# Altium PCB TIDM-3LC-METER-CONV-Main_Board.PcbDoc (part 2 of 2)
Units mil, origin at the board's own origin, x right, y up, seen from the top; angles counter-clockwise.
Board outline 4050 x 4800 mil, 4 copper layers (Top Layer, Mid-Layer 1, Mid-Layer 2, Bottom Layer); 180 components, 206 nets, 819 pads, 257 vias.
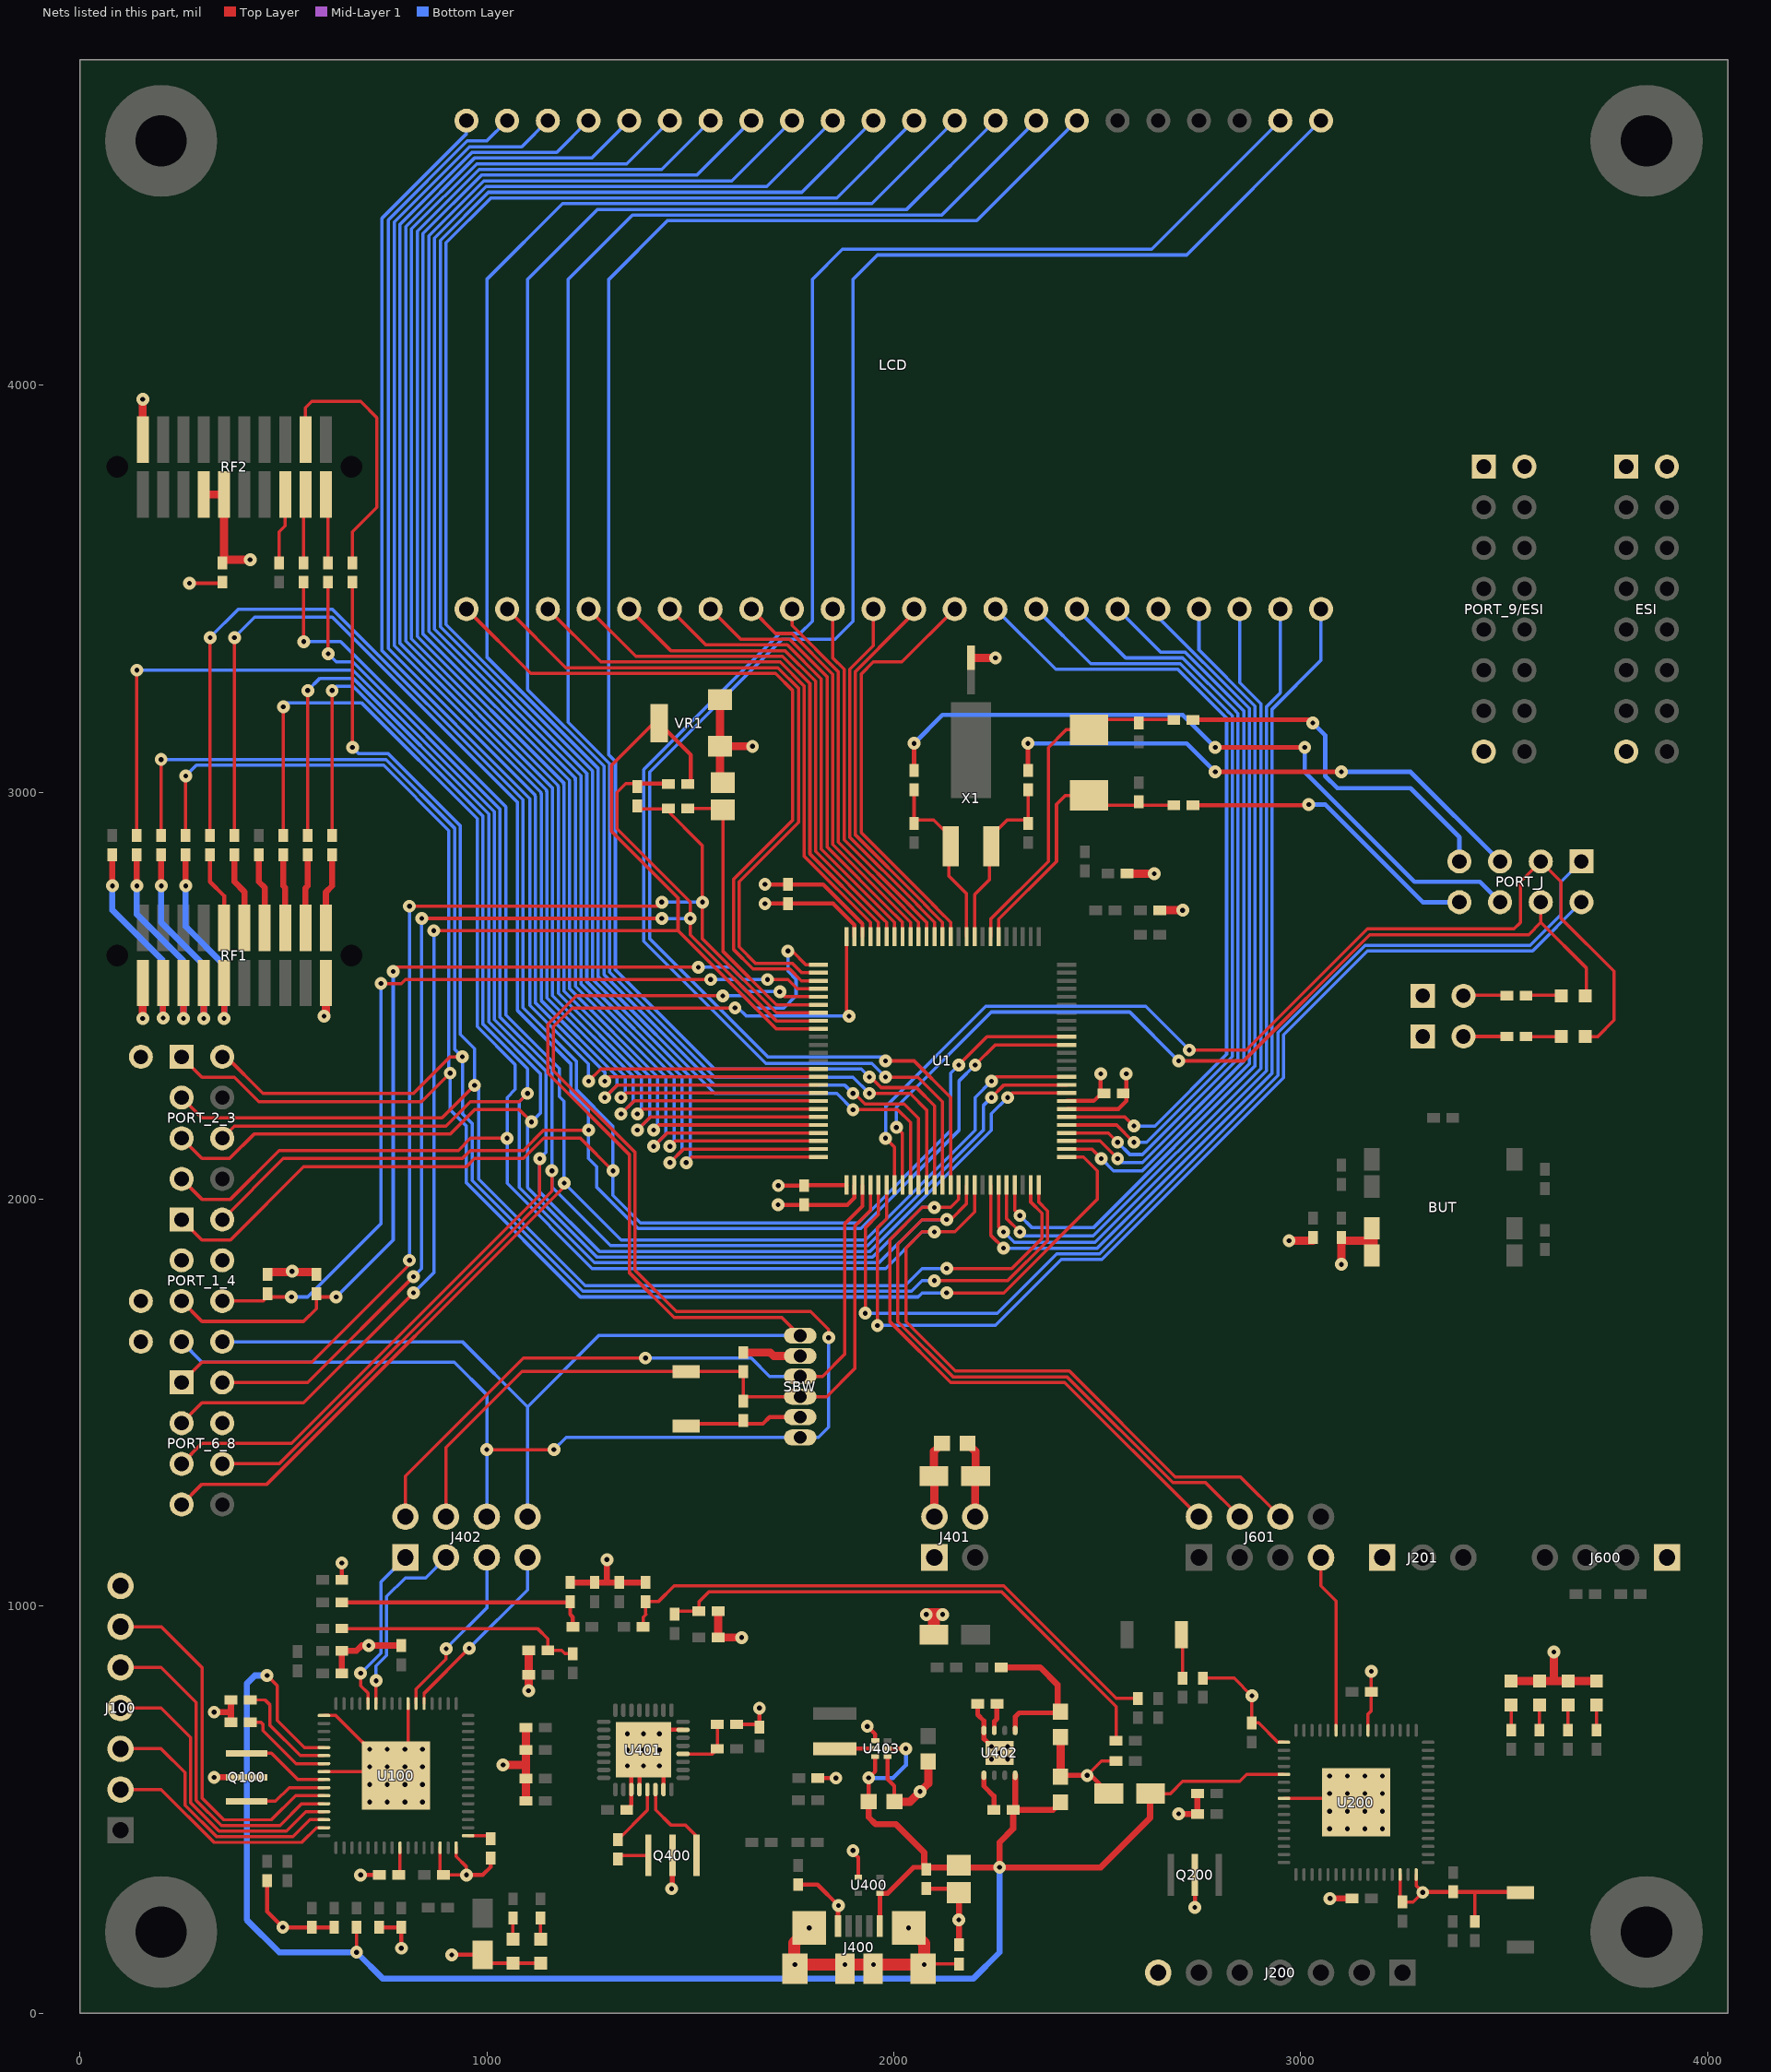
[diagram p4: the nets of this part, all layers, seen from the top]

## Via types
v1: diameter 31.5, hole 11.81, Top Layer to Bottom Layer, tented both sides, 211 vias
v2: diameter 31.5, hole 11.81, Top Layer to Bottom Layer, tented bottom, 41 vias
v3: diameter 23.81, hole 11.81, Top Layer to Bottom Layer, tented bottom, 5 vias

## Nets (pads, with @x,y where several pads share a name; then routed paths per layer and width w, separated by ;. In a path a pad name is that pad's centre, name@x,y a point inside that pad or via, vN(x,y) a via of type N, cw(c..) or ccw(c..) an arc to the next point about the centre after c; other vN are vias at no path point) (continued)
EZFET_SBW_RST: J402.3 U100.43 | length 473.6
  Top Layer w7.87: U100.43@727.79,761.17 v1(727.79,817.21) ; J402.3@900,1130 J402.3@910,1140
  Bottom Layer w7.87: v1(727.79,817.21) 727.79,853.17 753.87,879.25 753.87,1023.87 800,1070 850,1070 J402.3@900,1120
EZFET_SBW_TST: J402.1 U100.44 | length 412.5
  Top Layer w7.87: v1(690,836) 690,805 708.1,786.9 U100.44@708.1,761.17
  Bottom Layer w7.87: v1(690,836) 691,836 740,885 740,1060 J402.1@800,1120
EZFET_TCK: J100.2 U100.63 | length 568.6
  Top Layer w7.87: J100.2@100,550 200,550 330,420 545,420 581.05,456.05 U100.63@599.83,456.05
EZFET_TDI: J100.4 U100.61 | length 738.7
  Top Layer w7.87: J100.4@100,750 200,750 272.25,677.75 272.25,517.37 341.87,447.75 507.75,447.75 555.42,495.42 U100.61@599.83,495.42
EZFET_TDO: J100.5 U100.60 | length 823.9
  Top Layer w7.87: J100.5@100,850 200,850 286.13,763.87 286.13,523.12 347.62,461.62 491.62,461.62 545.1,515.1 U100.60@599.83,515.1
EZFET_TEST: J100.6 U100.59 | length 908.8
  Top Layer w7.87: J100.6@100,950 200,950 300,850 300,529.54 354.04,475.5 470.5,475.5 530,535 565,535 565.21,534.79 U100.59@599.83,534.79
EZFET_TMS: J100.3 U100.62 | length 653.6
  Top Layer w7.87: J100.3@100,650 200,650 258.38,591.62 258.38,511.62 336.13,433.87 523.87,433.87 565.73,475.73 U100.62@599.83,475.73
EZFET_UART_RXD: J402.5 U100.38 | length 430.8
  Top Layer w7.87: U100.38@826.21,761.17 826.21,796.21 900,870 v1(900,896)
  Bottom Layer w7.87: v1(900,896) 1000,996 J402.5@1000,1120
EZFET_UART_TXD: J402.7 U100.37 | length 464.1
  Top Layer w7.87: U100.37@845.9,761.17 845.9,785.9 v1(957,897)
  Bottom Layer w7.87: v1(957,897) 1100,1040 J402.7@1100,1120
EZFET_V18: C106.1 U100.55 | length 232
  Top Layer w7.87: C106.1@418.62,715 445,715 450,710 450,695 531.47,613.53 U100.55@599.83,613.53
EZFET_VCORE: C107.1 U100.17 | length 59
  Top Layer w7.87: U100.17@954.16,436.36 1002.26,436.36 C107.1@1010,428.62
EZFET_VREF: C108.1 U100.9 | length 72.6
  Top Layer w7.87: U100.9@786.84,406.83 786.84,336.78 C108.1@788.62,335
EZFET_VUSB: C105.1 U100.54 | length 267.2
  Top Layer w7.87: C105.1@418.62,770 455,770 467.5,757.5 467.5,707.5 541.79,633.21 U100.54@599.83,633.21
EZFET_XT2IN: Q100.1 U100.57 | length 216.7
  Top Layer w7.87: Q100.1@410,639.06 470.94,639.06 535.84,574.16 U100.57@599.83,574.16
EZFET_XT2OUT: Q100.3 U100.58 | length 203.7
  Top Layer w7.87: Q100.3@410,520.94 480.94,520.94 514.47,554.47 U100.58@599.83,554.47
GND: C100.2 C101.2 C102.2 C103.2 C104.2 C105.2 C106.2 C107.2 C108.2 C109.2 C110.2 C111.2 C200.2 C201.2 C202.2 C203.2 C204.2 C205.2 C206.2 C207.2 C208.2 C209.2 C210.2 C400.2 C401.2 C402.2 C403.2 C404.2 C405.2 C406.2 C407.2 C408.2 C410.2 C412.2 C414.2 C415.2 C416.2 C417.2 C418.2 D100.2 D101.2 D200.2 D201.2 D202.2 D203.2 J100.7 J200.7 J201.1 J400.5 J401.1 J600.1 Q100.2 Q200.2 Q400.2 R102.2 R107.1 R109.1 R210.1 R400.1 R401.1 R402.1 R403.1 R405.2 R410.1 R411.1 R414.1 R415.1 S201.1 U100.14 U100.16 U100.39 U100.49 U100.56 U100.65 U200.14 U200.16 U200.39 U200.49 U200.56 U200.65 U400.4 U401.7 U401.27 U401.28 U401.31 U401.33 U402.4 U402.9 U403.1 U403.4 | length 6226.4
  Top Layer w7.87: R210.1@2760,823.62 2836.38,823.62 v1(2880,780) C200.2@2880,713.62 2896.38,713.62 2944.12,665.88 U200.49@2958.92,665.88 ; U200.56@2958.92,528.08 3061.92,528.08 3071.76,518.24 U200.65@3136.08,518.24 v2(3157.73,539.9) U200.65@3165.61,547.77 ; U200.39@3165.61,695.41 3165.61,735.61 3173.62,743.62 C202.2@3173.62,790 v1(3173.62,840) ; U200.14@3244.35,341.08 3244.35,273.62 3276.46,273.62 v1(3300,297.16) 3283.72,313.44 U200.16@3283.72,341.08 ; C210.2@3428.19,225.78 3428.19,296.73
  Top Layer w8: U100.56@599.83,593.84 767.16,593.84 U100.65@777,584 ; U100.49@599.83,731.64 629.36,731.64 v2(755.35,605.65) ; U100.65@806.53,613.53 U100.39@806.53,761.17 ; U100.14@885.27,406.83 885.27,348.35 C102.2@893.62,340 v1(950,340) 950,360 924.64,385.36 U100.16@924.64,406.83 ; v1(2475.35,584.65) 2510.71,620 C201.2@2546.38,620
  Top Layer w10: C111.2@460,326.38 460,250 v1(498.62,211.38) R109.1@570,211.38 C110.2@625,211.38 ; C101.2@643.62,1065 v1(643.62,1106.38) ; v1(690,340) C108.2@736.38,340 ; C109.2@735,211.38 R107.1@790,211.38 v1(790,160) ; U100.65@777,584 v2(798.65,605.65) U100.65@806.53,613.53 ; v1(913.82,143.82) C103.2@990,143.82 1010.65,123.17 D100.2@1064.44,123.17 D101.2@1132.16,123.17 ; v1(950,340) 990,340 1010,360 C107.2@1010,381.38 C107.2@1010,391.38 ; C408.2@1343.62,500 1355.32,511.69 U401.27@1355.32,549.84 1355.32,598.07 v2(1345.47,607.91) ; U401.28@1375,549.84 1375,598.07 v2(1384.84,607.91) ; v2(1424.21,607.91) 1434.06,598.07 U401.31@1434.06,549.84 ; v2(1424.21,686.65) 1434.06,696.5 U401.7@1482.28,696.5 ; C400.2@1613.62,710 1663.62,710 C407.2@1670,703.62 v1(1670,750) ; C403.2@1765,316.38 1812.76,316.38 v1(1864.45,264.68) ; C404.2@1813.62,578 v1(1858,578) ; v1(1900,400) 1900,395.75 1912.87,382.87 U400.4@1912.87,334.37 ; v1(1935,705) 1954.68,685.32 U403.1@1954.68,670 ; U403.4@1985,630.63 1985,575.16 2001.34,558.82 C415.2@2001.34,520 ; C402.2@2080,306.38 2140.16,306.38 C401.2@2160,286.54 ; v1@2484.17,584.65 C209.2@2528.82,540 ; v1(2740,260) Q200.2@2740,340 ; U200.65@3136.08,518.24 v2(3201.04,453.28) U200.65@3201.92,454.16 ; v1(3300,297.16) 3301.38,298.54 C208.2@3375,298.54 3538.39,298.54 S201.1@3540,296.93
  Top Layer w12: v1(1454.15,306.15) 1456,308 Q400.2@1456,388 ; J400.5@1863.27,214.68 v1@1863.27,263.5 ; C416.2@2206.38,760 2206.38,733.62 2221.61,718.39 U402.4@2221.61,695.12 2221.61,674.45 v3(2240.32,655.75) ; C414.2@2410,584.65 v1(2475.35,584.65)
  Top Layer w15: v1(330,580) Q100.2@410,580 ; v1(330,740) 371.38,740 ; C106.2@371.38,715 371.38,740 ; C105.2@371.38,770 371.38,740 ; C100.2@643.62,835.5 R102.2@643.62,890.5 679.5,890.5 692.62,903.62 C104.2@790,903.62 ; R411.1@1205,1058.62 C406.2@1265,1058.62 1295.25,1058.62 ; v1(1295.25,1114.75) 1295.25,1058.62 ; R414.1@1390.5,1058.62 C410.2@1325.5,1058.62 1295.25,1058.62 ; R405.2@2160,168.62 C401.2@2160,286.54 ; v1(2700,490) C207.2@2746.38,490 C206.2@2746.38,540 ; v1(3072.16,282.16) C204.2@3126.38,282.16
  Top Layer w20: v1(1040,610) 1096.22,610 ; R402.1@1096.22,521.97 R403.1@1096.22,576.97 1096.22,610 ; R401.1@1096.22,701.97 R400.1@1096.22,646.97 1096.22,610 ; v1(1102.69,792.69) C405.2@1102.69,831.65 R410.1@1102.69,891.65 ; R415.1@1568.62,988.35 1568.62,961.38 C412.2@1568.62,923.35 v1(1626.65,923.35) ; C415.2@2001.34,520 2040,520 v1(2065,545) 2085,565 C417.2@2085,610 ; C418.2@2402.42,678.15 2410,670.57 C414.2@2410,584.65 ; D203.2@3517,816.69 D202.2@3587,816.69 3622,816.69 ; v1(3622,888) 3622,816.69 ; D200.2@3727,816.69 D201.2@3657,816.69 3622,816.69
  Top Layer w30: v1(2080,980) v1(2120,980) ; C203.2@2098.82,930 2098.82,978.82
  other v1: 2160,230 710,903.62
  other v2: 3071.12,453.28 3114.43,453.28 3157.73,453.28 3071.12,496.59 3114.43,496.59 3157.73,496.59 3201.04,496.59 712.04,519.04 755.35,519.04 798.65,519.04 841.96,519.04 3071.12,539.9 3114.43,539.9 3201.04,539.9 712.04,562.35 755.35,562.35 798.65,562.35 841.96,562.35 3071.12,583.2 3114.43,583.2 3157.73,583.2 3201.04,583.2 712.04,605.65 841.96,605.65 1345.47,647.28 1384.84,647.28 1424.21,647.28 712.04,648.96 755.35,648.96 798.65,648.96 841.96,648.96 1345.47,686.65 1384.84,686.65
  other v3: 2240.32,624.25 2279.68,624.26 2260,640 2279.68,655.75
HFXIN: PORT_J.7 R61.1 | length 884.4
  Top Layer w11.02: R61.1@2743.49,3178 3022,3178 v1(3030,3170)
  Bottom Layer w11.02: v1(3030,3170) 3060,3140 3060,3040 3090,3010 3270,3010 3390,2890 PORT_J.7@3390,2830
HFXOUT: PORT_J.8 R62.1 | length 747.9
  Top Layer w11.02: R62.1@2743.49,2968 3020,2968 v1(3020,2970)
  Bottom Layer w11.02: v1(3020,2970) 3060,2970 3300,2730 PORT_J.8@3390,2730
HUB_DM1: R203.1 R415.2 R417.1 | length 1322.1
  Top Layer w7.87: R417.1@1461.65,980.43 1469.57,988.35 R415.2@1521.38,988.35 1521.38,1011.38 1546.13,1036.13 2264.25,1036.13 2546.38,754 R203.1@2546.38,670
HUB_DM2: R101.1 R411.2 R413.1 | length 626
  Top Layer w10: R101.1@643.62,1010 1203.62,1010 R411.2@1205,1011.38 1205,980 1211.38,973.62 R413.1@1211.38,950
HUB_DP1: R201.1 R414.2 R416.1 | length 1404.4
  Top Layer w7.87: R416.1@1384.12,950 1384.12,973.12 1391,980 1390.5,980.5 R414.2@1390.5,1011.38 1421.38,1011.38 1460,1050 2270,1050 2546.38,773.62 R201.1@2600,773.62
HUB_DP2: R100.1 R410.2 R412.1 | length 610
  Top Layer w7.87: R410.2@1149.93,891.65 1184.16,891.65 1192.19,883.62 R412.1@1211.31,883.62
  Top Layer w8: R100.1@643.62,945.5 1124.5,945.5 1149.93,920.07 R410.2@1149.93,891.65
HUB_R\E\S\E\T\: C400.1 R404.1 U401.4 | length 149.3
  Top Layer w8: U401.4@1482.28,637.44 1553.82,637.44 R404.1@1566.38,650 C400.1@1566.38,710
HUB_XTAL1: Q400.1 U401.30 | length 232.2
  Top Layer w7.87: U401.30@1414.37,549.84 1415,549.21 1415,500 1452,463 1488,463 1514.06,436.94 Q400.1@1514.06,380
HUB_XTAL2: R406.2 U401.29 | length 153.3
  Top Layer w7.87: R406.2@1322,426.62 1394.69,499.31 U401.29@1394.69,549.84
I2C_SCL: PORT_1_4.6 R40.1 U1.5 | length 2189.5
  Top Layer w8: PORT_1_4.6@350,1750 451.49,1750 461.49,1760 v1(520,1760) ; v1(740,2530) 790,2530 800,2540 1560,2540 1550,2530 v1(1550,2540) ; v1(1720,2510) 1732.52,2497.48 U1.5@1814.88,2497.48
  Bottom Layer w8: v1(520,1760) 560,1760 740,1940 v1(740,2530) ; v1(1550,2540) 1609.8,2540 1639.8,2510 v1(1720,2510)
I2C_SDA: PORT_1_4.5 R41.1 U1.4 | length 2371.2
  Top Layer w8: PORT_1_4.5@250,1750 300,1700 550,1700 581.49,1731.49 581.49,1760 v1(630,1760) ; v1(770,2560) 780,2570 v1(1520,2570) ; v1(1690,2540) 1740,2540 1762.83,2517.17 U1.4@1814.88,2517.17
  Bottom Layer w8: v1(630,1760) 770,1900 v1(770,2560) ; v1(1520,2570) 1599.6,2570 1629.6,2540 v1(1690,2540)
LCD0: LCD.1 U1.3 | length 1821.7
  Top Layer w8: LCD.1@950,3450 1108,3292 1709.41,3292 1752,3249.41 1752,2931.8 1606,2785.8 1606,2614.2 1654.2,2566 1744,2566 1773.15,2536.85 U1.3@1814.88,2536.85
LCD1: LCD.2 U1.2 | length 1713.5
  Top Layer w8: LCD.2@1050,3450 1194,3306 1715.21,3306 1766,3255.21 1766,2926 1620,2780 1620,2620 1660,2580 1750,2580 1773.46,2556.54 U1.2@1814.88,2556.54
LCD2: LCD.3 U1.97 | length 1391.6
  Top Layer w8: LCD.3@1150,3450 1280,3320 1721.01,3320 1780,3261.01 1780,2842.83 1942.83,2680 U1.97@1942.83,2645.12
LCD3: LCD.4 U1.96 | length 1311.4
  Top Layer w8: LCD.4@1250,3450 1366,3334 1726.8,3334 1794,3266.8 1794,2848.63 1956.83,2685.8 1956.83,2685.69 1962.52,2680 U1.96@1962.52,2645.12
LCD4: LCD.5 U1.95 | length 1231.1
  Top Layer w8: LCD.5@1350,3450 1452,3348 1732.6,3348 1808,3272.6 1808,2854.43 1970.83,2691.6 1970.83,2691.48 1976.52,2685.8 1976.52,2685.68 1982.2,2680 U1.95@1982.2,2645.12
LCD5: LCD.6 U1.94 | length 1150.9
  Top Layer w8: LCD.6@1450,3450 1538,3362 1738.4,3362 1822,3278.4 1822,2860.23 1984.83,2697.4 1984.83,2697.28 1990.52,2691.6 1990.52,2691.48 1996.2,2685.8 1996.2,2685.69 2001.89,2680 U1.94@2001.89,2645.12
LCD6: LCD.7 U1.93 | length 1070.6
  Top Layer w8: LCD.7@1550,3450 1624,3376 1744.2,3376 1836,3284.2 1836,2866.03 1998.83,2703.2 1998.83,2703.08 2004.52,2697.4 2004.52,2697.28 2010.2,2691.6 2010.2,2691.48 2015.89,2685.8 2015.89,2685.69 2021.58,2680 U1.93@2021.58,2645.12
LCD7: LCD.8 U1.92 | length 990.4
  Top Layer w8: LCD.8@1650,3450 1710,3390 1750,3390 1850,3290 1850,2871.83 2012.83,2708.99 2012.83,2708.88 2018.52,2703.2 2018.52,2703.08 2024.2,2697.4 2024.2,2697.28 2029.89,2691.6 2029.89,2691.48 2035.58,2685.8 2035.58,2685.68 2041.26,2680 U1.92@2041.26,2645.12
LCD8: LCD.9 U1.91 | length 933.7
  Top Layer w8: LCD.9@1750,3450 1750,3410 1864,3296 1864,2877.63 2026.83,2714.79 2026.83,2714.68 2032.52,2708.99 2032.52,2708.88 2038.2,2703.2 2038.2,2703.08 2043.89,2697.4 2043.89,2697.28 2049.58,2691.6 2049.58,2691.48 2055.26,2685.8 2055.26,2685.69 2060.95,2680 U1.91@2060.95,2645.12
LCD9: LCD.10 U1.90 | length 900.4
  Top Layer w8: LCD.10@1850,3450 1850,3330 1878,3302 1878,2883.43 2040.83,2720.59 2040.83,2720.48 2046.52,2714.79 2046.52,2714.68 2052.2,2708.99 2052.2,2708.88 2057.89,2703.2 2057.89,2703.08 2063.58,2697.4 2063.58,2697.28 2069.26,2691.6 2069.26,2691.48 2074.95,2685.8 2074.95,2685.68 2080.63,2680 U1.90@2080.63,2645.12
LCD10: LCD.11 U1.89 | length 915.2
  Top Layer w8: LCD.11@1950,3450 1950,3360 1892,3302 1892,2889.23 2054.83,2726.39 2054.83,2726.28 2060.52,2720.59 2060.52,2720.48 2066.2,2714.79 2066.2,2714.68 2071.89,2708.99 2071.89,2708.88 2077.58,2703.2 2077.58,2703.08 2083.26,2697.4 2083.26,2697.28 2088.95,2691.6 2088.95,2691.48 2094.63,2685.8 2094.63,2685.69 2100.32,2680 U1.89@2100.32,2645.12
LCD11: LCD.12 U1.88 | length 953.2
  Top Layer w8: LCD.12@2050,3450 2050,3441 1964,3355 1964,3354.2 1906,3296.2 1906,2895.02 2068.83,2732.19 2068.83,2732.08 2074.52,2726.39 2074.52,2726.28 2080.2,2720.59 2080.2,2720.48 2085.89,2714.79 2085.89,2714.68 2091.58,2708.99 2091.58,2708.88 2097.26,2703.2 2097.26,2703.08 2102.95,2697.4 2102.95,2697.28 2108.63,2691.6 2108.63,2691.48 2114.32,2685.8 2114.32,2685.68 2120,2680 U1.88@2120,2645.12
LCD12: LCD.13 U1.87 | length 1032.4
  Top Layer w8: U1.87@2139.69,2645.12 2139.69,2680 2134,2685.69 2134,2685.8 2128.32,2691.48 2128.32,2691.6 2122.63,2697.28 2122.63,2697.4 2116.95,2703.08 2116.95,2703.2 2111.26,2708.88 2111.26,2708.99 2105.58,2714.68 2105.58,2714.79 2099.89,2720.48 2099.89,2720.59 2094.2,2726.28 2094.2,2726.39 2088.52,2732.08 2088.52,2732.19 2082.83,2737.88 2082.83,2737.99 1920,2900.82 1920,3290.4 1949.6,3320 2020,3320 LCD.13@2150,3450
LCD13: LCD.14 U1.56 | length 1979.8
  Top Layer w8: U1.56@2425.12,2202.2 2567.8,2202.2 v1(2590,2180)
  Bottom Layer w8: LCD.14@2250,3450 2398,3302 2698,3302 2818,3182 2818,2356.39 2641.61,2180 v1(2590,2180)
LCD14: LCD.15 U1.55 | length 1939.7
  Top Layer w8: U1.55@2425.12,2182.52 2547.48,2182.52 v1(2590,2140)
  Bottom Layer w8: LCD.15@2350,3450 2484,3316 2704,3316 2820,3200 2820,3199.8 2832,3187.8 2832,2350.59 2621.41,2140 v1(2590,2140)
LCD15: LCD.16 U1.54 | length 1891.3
  Top Layer w8: U1.54@2425.12,2162.83 2527.17,2162.83 v1(2550,2140)
  Bottom Layer w8: LCD.16@2450,3450 2570,3330 2710,3330 2840,3200 2840,3199.6 2846,3193.6 2846,2344.79 2611.21,2110 2580,2110 v1(2550,2140)
LCD16: LCD.17 U1.53 | length 1834.6
  Top Layer w8: U1.53@2425.12,2143.15 2506.85,2143.15 v1(2550,2100)
  Bottom Layer w8: v1(2550,2100) 2560,2090 2611.01,2090 2860,2338.99 2860,3200 2716,3344 2656,3344 LCD.17@2550,3450
LCD17: LCD.18 U1.52 | length 1789.6
  Top Layer w8: U1.52@2425.12,2123.46 2486.54,2123.46 v1(2510,2100)
  Bottom Layer w8: v1(2510,2100) 2540,2070 2610.8,2070 2874,2333.2 2874,3205.8 2650,3429.8 LCD.18@2650,3450
LCD18: LCD.19 U1.47@2297.17,2034.88 | length 2015
  Top Layer w8: U1.47@2297.17,2034.88 2297.17,1972.83 v1(2310,1960)
  Bottom Layer w8: v1(2310,1960) 2340,1930 2490.6,1930 2888,2327.4 2888,3211.6 2750,3349.6 LCD.19@2750,3450
LCD19: LCD.20 U1.46 | length 2045.3
  Top Layer w8: U1.46@2277.48,2034.88 2277.48,1952.52 v1(2310,1920)
  Bottom Layer w8: v1(2310,1920) 2320,1910 2490.4,1910 2902,2321.6 2902,3215.8 2902.5,3216.3 2902,3216.79 2902,3217.4 2850,3269.4 LCD.20@2850,3450
LCD20: LCD.21 U1.45 | length 2099.7
  Top Layer w8: U1.45@2257.8,2034.88 2257.8,1932.2 v1(2270,1920)
  Bottom Layer w8: v1(2270,1920) 2296,1894 2494.2,1894 2916,2315.8 2916,3210 2950,3244 LCD.21@2950,3450
LCD21: LCD.22 U1.44 | length 2195.9
  Top Layer w8: U1.44@2238.11,2034.88 2238.11,1911.89 v1(2270,1880)
  Bottom Layer w8: v1(2270,1880) 2500,1880 2930,2310 2930,3204.2 3050,3324.2 LCD.22@3050,3450
LCD22: LCD.23 U1.39 | length 4331.3
  Top Layer w8: v1(1980,2340) 2050,2340 2139.68,2250.32 U1.39@2139.68,2034.88
  Bottom Layer w8: v1(1980,2340) 1970,2350 1690,2350 1400,2640 1400,3050 1726,3376 1856,3376 1900,3420 1900,4260 1960,4320 2720,4320 LCD.23@3050,4650
LCD23: LCD.24 U1.38 | length 4240.5
  Top Layer w8: v1(1980,2300) 2060,2300 2120,2240 U1.38@2120,2034.88
  Bottom Layer w8: v1(1980,2300) 1946,2334 1686,2334 1386,2634 1386,3055.8 1720.2,3390 1770,3390 1800,3420 1800,4260 1874,4334 2634,4334 LCD.24@2950,4650
LCD24: LCD.29 U1.37 | length 4132.1
  Top Layer w8: v1(1940,2300) 1943.59,2300 1969.33,2274.25 2055.75,2274.25 2100.31,2229.69 U1.37@2100.31,2034.88
  Bottom Layer w8: v1(1940,2300) 1920,2320 1559.51,2320 1316,2563.51 1316,3075.56 1300,3091.56 1300,4260 1444,4404 2204,4404 LCD.29@2450,4650
LCD25: LCD.30 U1.36 | length 4159.3
  Top Layer w8: v1(1940,2260) 2040,2260 2080.63,2219.37 U1.36@2080.63,2034.88
  Bottom Layer w8: v1(1940,2260) 1900,2300 1559.71,2300 1302,2557.71 1302,3069.76 1200,3171.76 1200,4260 1358,4418 2118,4418 LCD.30@2350,4650
LCD26: LCD.31 U1.35 | length 4180.8
  Top Layer w8: v1(1900,2260) 1903.59,2260 1929.33,2234.25 2025.75,2234.25 2060.94,2199.06 U1.35@2060.94,2034.88
  Bottom Layer w8: v1(1900,2260) 1880,2280 1559.91,2280 1288,2551.91 1288,3063.97 1100,3251.97 1100,4260 1272,4432 2032,4432 LCD.31@2250,4650
LCD27: LCD.32 U1.34 | length 4208.1
  Top Layer w8: v1(1900,2220) 2010,2220 2041.26,2188.74 U1.34@2041.26,2034.88
  Bottom Layer w8: v1(1900,2220) 1860,2260 1560.11,2260 1274,2546.11 1274,3058.17 1000,3332.17 1000,4260 1186,4446 1946,4446 LCD.32@2150,4650
LCD28: LCD.33 U1.25 | length 4127.5
  Top Layer w8: v1@1480,2090 v1(1490,2090) 1503.78,2103.78 U1.25@1814.88,2103.78
  Bottom Layer w8: v1(1490,2090) 1500,2100 1500,2300.31 1260,2540.31 1260,3052.37 900,3412.37 900,4350 1010,4460 1860,4460 LCD.33@2050,4650
LCD29: LCD.34 U1.24 | length 4089.1
  Top Layer w8: v1(1450,2090) 1483.46,2123.46 U1.24@1814.88,2123.46
  Bottom Layer w8: v1(1450,2090) 1480,2120 1480,2300.52 1245.72,2534.8 1245.72,3046.45 885.72,3406.45 885.72,4355.51 1004.2,4474 1774,4474 LCD.34@1950,4650
LCD30: LCD.35 U1.23 | length 3957.4
  Top Layer w8: v1@1440,2130 v1(1450,2130) 1463.15,2143.15 U1.23@1814.88,2143.15
  Bottom Layer w8: v1(1450,2130) 1460,2140 1460,2300.72 1231.72,2529 1231.72,3036.47 1231.57,3036.62 1231.57,3040.59 871.57,3400.59 871.57,4361.17 998.4,4488 1688,4488 LCD.35@1850,4650
LCD31: LCD.36 U1.22 | length 3918.9
  Top Layer w8: v1(1410,2130) 1442.83,2162.83 U1.22@1814.88,2162.83
  Bottom Layer w8: v1(1410,2130) 1440,2160 1440,2300.92 1217.72,2523.2 1217.72,3030.68 1217.43,3030.96 1217.43,3034.73 857.43,3394.73 857.43,4366.83 992.6,4502 1602,4502 LCD.36@1750,4650
LCD32: LCD.37 U1.21 | length 3777.2
  Top Layer w8: v1(1410,2170) 1422.52,2182.52 U1.21@1814.88,2182.52
  Bottom Layer w8: v1(1410,2170) 1420,2180 1420,2301.12 1203.72,2517.4 1203.72,3024.88 1203.29,3025.3 1203.29,3028.88 843.29,3388.88 843.29,4372.48 986.8,4516 1516,4516 LCD.37@1650,4650
LCD33: LCD.38 U1.20 | length 3748.7
  Top Layer w8: v1(1370,2170) 1402.2,2202.2 U1.20@1814.88,2202.2
  Bottom Layer w8: v1(1370,2170) 1400,2200 1400,2301.32 1189.72,2511.6 1189.72,3019.08 1189.15,3019.65 1189.15,3023.02 829.15,3383.02 829.15,4378.14 981.01,4530 1430,4530 LCD.38@1550,4650
LCD34: LCD.39 U1.19 | length 3607
  Top Layer w8: v1(1370,2210) 1381.89,2221.89 U1.19@1814.88,2221.89
  Bottom Layer w8: v1(1370,2210) 1380,2220 1380,2301.52 1175.72,2505.8 1175.72,3013.28 1175.01,3013.99 1175.01,3017.16 815.01,3377.16 815.01,4383.8 975.21,4544 1344,4544 LCD.39@1450,4650
LCD35: LCD.40 U1.18 | length 3578.5
  Top Layer w8: v1(1330,2210) 1361.57,2241.57 U1.18@1814.88,2241.57
  Bottom Layer w8: v1(1330,2210) 1360,2240 1360,2301.72 1161.72,2500.01 1161.72,3007.48 1160.86,3008.33 1160.86,3011.3 800.86,3371.3 800.86,4389.46 969.41,4558 1258,4558 LCD.40@1350,4650
LCD36: LCD.41 U1.17 | length 3446.7
  Top Layer w8: v1@1320,2250 v1(1330,2250) 1341.26,2261.26 U1.17@1814.88,2261.26
  Bottom Layer w8: LCD.41@1250,4650 1172,4572 963.61,4572 786.86,4395.25 786.86,3365.5 1138.66,3013.71 1146.86,3005.5 1146.86,3002.53 1147.72,3001.68 1147.72,2494.21 1340,2301.92 1340,2260 v1(1330,2250)
LCD37: LCD.42 U1.16 | length 3408.1
  Top Layer w8: v1(1290,2250) 1320.94,2280.94 U1.16@1814.88,2280.94
  Bottom Layer w8: LCD.42@1150,4650 1086,4586 957.81,4586 772.86,4401.05 772.86,3359.71 1132.86,2999.71 1132.86,2996.73 1133.72,2995.88 1133.72,2488.41 1320,2302.12 1320,2280 v1(1290,2250)
LCD38: LCD.43 U1.15 | length 3258.7
  Top Layer w8: v1(1290,2290) 1300.63,2300.63 U1.15@1814.88,2300.63
  Bottom Layer w8: LCD.43@1050,4650 1000,4600 952.01,4600 757.96,4405.95 757.96,3353.53 1117.96,2993.53 1117.96,2991.84 1119.72,2990.08 1119.72,2482.61 1290,2312.32 v1(1290,2290)
LCD39: LCD.44 U1.14 | length 3233.4
  Top Layer w8: v1(1250,2290) 1280.31,2320.31 U1.14@1814.88,2320.31
  Bottom Layer w8: LCD.44@950,4650 950,4617.79 742.76,4410.55 742.76,3347.24 1105.72,2984.28 1105.72,2476.81 1250,2332.53 v1(1250,2290)
LDO_3V3: C418.1 R419.2 U402.1 | length 354.3
  Top Layer w12: U402.1@2298.39,695.12 2298.39,728.39 2308.43,738.43 C418.1@2392.42,738.43
  Top Layer w15: R419.2@2263.62,850 2360,850 2402.42,807.58 C418.1@2402.42,741.14
LED1: LED1.2 PORT_J.3 U1.32 | length 2758.2
  Top Layer w8: v1(1980,2150) 2001.89,2128.11 U1.32@2001.89,2034.88 ; v1(2726.51,2366.51) 2866.51,2366.51 3164.1,2664.1 3524.3,2664.1 3540.1,2679.9 3540.1,2780.1 PORT_J.3@3590,2830 3640,2780 3640,2690 3770,2560 3770,2440 3729,2399 LED1.2@3702.5,2399
  Bottom Layer w8: v1(1980,2150) 1980,2227.84 2226.16,2474 2619.03,2474 v1(2726.51,2366.51)
LED2: LED2.2 PORT_J.4 U1.33 | length 2344.2
  Top Layer w8: v1(2006.51,2176.51) 2021.57,2161.45 U1.33@2021.57,2034.88 ; v1(2700,2340) 2859.8,2340 3169.9,2650.1 3560.1,2650.1 3590,2680 ; PORT_J.4@3590,2730 3590,2680 ; LED2.2@3702.5,2501 3702.5,2567.5 3590,2680
  Bottom Layer w8: v1(2006.51,2176.51) 2006.51,2226.51 2240,2460 2580,2460 v1(2700,2340)
LFXIN: PORT_J.5 R60.2 | length 1338.6
  Top Layer w11.02: R60.2@2330,3061.5 v1(2330,3120) ; v1(2790,3050) v1(3100,3050)
  Bottom Layer w11.02: v1(2330,3120) 2720,3120 v1(2790,3050) ; v1(3100,3050) 3270,3050 PORT_J.5@3490,2830
LFXOUT: PORT_J.6 R59.2 | length 1753.2
  Top Layer w11.02: R59.2@2050,3061.5 v1(2050,3120) ; v1(2790,3110) v1(3010,3110)
  Bottom Layer w11.02: v1(2050,3120) 2120,3190 2710,3190 v1(2790,3110) ; v1(3010,3110) 3010,3050 3280,2780 3440,2780 PORT_J.6@3490,2730
NetC10_2: C10.2 R59.1 U1.85 X1.1 | length 437.3
  Top Layer w8: R59.1@2050,2998.51 2050,2931.5 2098.5,2931.5 2140,2890 X1.1@2140,2867.44 ; X1.1@2135,2867.44 2135,2795 2179.06,2750.94 U1.85@2179.06,2645.12
NetC11_1: C11.1 R60.1 U1.84 X1.2 | length 435.8
  Top Layer w8: U1.84@2198.74,2645.12 2198.74,2748.74 2235,2785 X1.2@2235,2867.44 ; X1.2@2240,2867.44 2240,2892.82 2278.68,2931.49 2330,2931.49 R60.1@2330,2998.51
NetC12_2: C12.2 R61.2 U1.82 X2.1 | length 852.7
  Top Layer w8: U1.82@2238.11,2645.12 2238.11,2688.11 2380,2830 2380,3110 2423.71,3153.71 X2.1@2480,3153.71 2504.79,3178.5 2602,3178.5 2680,3178.5 R61.2@2680.5,3178
NetC13_1: C13.1 R62.2 U1.81 X2.2 | length 683.6
  Top Layer w8: U1.81@2257.8,2645.12 2257.8,2688 2400,2830.2 2400,2970 2422.29,2992.29 X2.2@2480,2992.29 2503.79,2968.51 2602,2968.51 2679.99,2968.51 R62.2@2680.5,2968
NetC33_2: C33.2 R11.2 U1.6 | length 721.4
  Top Layer w8: R11.2@1504.96,2956.54 1501.5,2960 1576.53,2960 C33.2@1580,2956.54 1580,2609.4 1711.6,2477.8 U1.6@1814.88,2477.8
NetC416_1: C416.1 U402.3 | length 67.5
  Top Layer w12: U402.3@2247.2,695.12 2247.2,717.2 2253.62,723.62 C416.1@2253.62,760
NetD100_1: D100.1 R104.1 | length 51.9
  Top Layer w7.87: D100.1@1064.44,182.22 R104.1@1064.44,234.07
NetD101_1: D101.1 R105.1 | length 51.9
  Top Layer w7.87: D101.1@1132.16,182.22 R105.1@1132.16,234.07
NetD200_1: D200.1 R200.1 | length 61.9
  Top Layer w7.87: R200.1@3727,695.78 D200.1@3727,757.64
NetD201_1: D201.1 R202.1 | length 61.9
  Top Layer w7.87: R202.1@3657,695.78 D201.1@3657,757.64
NetD202_1: D202.1 R204.1 | length 61.9
  Top Layer w7.87: R204.1@3587,695.78 D202.1@3587,757.64
NetD203_1: D203.1 R205.1 | length 61.9
  Top Layer w7.87: R205.1@3517,695.78 D203.1@3517,757.64
NetJP13_2: JP13.2 R9.1 | length 98.5
  Top Layer w8: JP13.2@3400,2400 R9.1@3498.5,2400
NetJP14_2: JP14.2 R10.1 | length 101.9
  Top Layer w8: JP14.2@3400,2500 3401,2501 R10.1@3501.51,2501
NetL400_1: L400.1 U403.2 | length 90.8
  Top Layer w10: L400.1@1864,650 1864.31,650.32 1874.84,650.32 U403.2@1954.68,650.32
NetLED1_1: LED1.1 R9.2 | length 75.4
  Top Layer w8: R9.2@3564.5,2398 3565.5,2399 LED1.1@3639.51,2399
NetLED2_1: LED2.1 R10.2 | length 75
  Top Layer w8: R10.2@3564.5,2501 LED2.1@3639.51,2501
NetQ400_3: Q400.3 R406.1 | length 78.5
  Top Layer w7.87: R406.1@1322,379.38 1330.62,388 Q400.3@1396.94,388
NetR44_1: R44.1 RF2.15 | length 166
  Top Layer w8: R44.1@490,3571.5 490,3640 504.5,3654.5 RF2.15@504.5,3731.5
NetR45_1: R45.1 RF2.17 | length 161.9
  Top Layer w8: R45.1@550,3571.5 550,3727 RF2.17@554.5,3731.5
NetR46_1: R46.1 RF2.19 | length 162.3
  Top Layer w8: RF2.19@604.5,3731.5 610,3726 R46.1@610,3571.5
NetR47_1: R47.1 RF2.18 | length 649.8
  Top Layer w8: RF2.18@554.5,3866.5 554.5,3944.5 570,3960 690,3960 730,3920 730,3700 670,3640 R47.1@670,3571.5
NetR48_1: R48.1 RF1.3 | length 530.6
  Top Layer w15: v1(80,2770) R48.1@80,2838.5 ; v1(204.5,2445.5) RF1.3@204.5,2531.5
  Bottom Layer w15: v1(80,2770) 80,2710 204.5,2585.5 v1(204.5,2445.5)
NetR49_1: R49.1 RF1.5 | length 528.4
  Top Layer w15: v1(140,2770) R49.1@140,2838.51 ; v1(254.5,2444.5) RF1.5@254.5,2531.5
  Bottom Layer w15: v1(140,2770) 140,2700 254.5,2585.5 v1(254.5,2444.5)
NetR50_1: R50.1 RF1.7 | length 524.3
  Top Layer w15: v1(200,2770) R50.1@200,2838.51 ; v1(304.5,2444.5) RF1.7@304.5,2531.5
  Bottom Layer w15: v1(200,2770) 200,2680 304.5,2575.5 v1(304.5,2444.5)
NetR51_1: R51.1 RF1.9 | length 520.2
  Top Layer w15: v1(260,2770) R51.1@260,2838.51 ; v1(354.5,2444.5) RF1.9@354.5,2531.5
  Bottom Layer w15: v1(260,2770) 260,2670 354.5,2575.5 v1(354.5,2444.5)
NetR52_1: R52.1 RF1.10 | length 186.3
  Top Layer w10: R52.1@320,2838.51 320,2780 354.5,2745.5 RF1.10@354.5,2666.5
NetR53_1: R53.1 RF1.12 | length 182.2
  Top Layer w15: R53.1@380,2838.51 380,2780 404.5,2755.5 RF1.12@404.5,2666.5
NetR54_1: R54.1 RF1.14 | length 178
  Top Layer w15: R54.1@440,2838.51 440,2780 454.5,2765.5 RF1.14@454.5,2666.5
NetR55_1: R55.1 RF1.16 | length 173.9
  Top Layer w15: R55.1@500,2838.51 500,2770 504.5,2765.5 RF1.16@504.5,2666.5
NetR56_1: R56.1 RF1.18 | length 174.3
  Top Layer w15: RF1.18@554.5,2666.5 554.5,2764.5 560,2770 R56.1@560,2838.51
NetR57_1: R57.1 RF1.20 | length 178.4
  Top Layer w15: RF1.20@604.5,2666.5 604.5,2754.5 620,2770 R57.1@620,2838.51
NetR211_2: R211.2 S202.1 | length 106.4
  Top Layer w8: R211.2@2710,823.62 S202.1@2710,930
NetR418_2: R418.2 U402.5 | length 95.1
  Top Layer w12: U402.5@2221.61,584.88 2221.61,558.39 2246.38,533.62 R418.2@2246.38,500
P6.0: PORT_6_8.1 R11.1 R12.2 U1.7 | length 3071.7
  Top Layer w8: PORT_6_8.1@250,1550 300,1600 570,1600 810,1840 v1(810,1850) ; v1(810,2720) 1420,2720 v1(1430,2730) ; R12.2@1370,2958.5 1437.01,2958.5 1438.51,2960 1530,2868.51 v1(1530,2730) 1530,2639.6 1711.49,2458.11 U1.7@1814.88,2458.11
  Bottom Layer w8: v1(810,1850) v1(810,2720) ; v1(1430,2730) v1(1530,2730)
P6.1: PORT_6_8.2 R12.1 R13.2 U1.8 | length 3091.2
  Top Layer w8: PORT_6_8.2@350,1550 560,1550 v1(820,1810) ; v1(840,2690) v1(1430,2690) ; R12.1@1370,3021.49 1341.49,3021.49 1320,3000 1320,2910 1500,2730 1500,2649.8 1711.37,2438.43 U1.8@1814.88,2438.43
  Top Layer w9.84: R12.1@1370,3021.49 1437.01,3021.49 R13.2@1438.5,3020
  Bottom Layer w8: v1(820,1810) 840,1830 v1@840,2700 ; v1(1430,2690) 1430.1,2689.9 v1(1500,2689.9)
P6.2: PORT_6_8.3 R13.1 U1.9 VR1.2 | length 3474.7
  Top Layer w8: PORT_6_8.3@250,1450 300,1500 550,1500 v1(820,1770) ; v1(870,2660) 1470,2660 ; VR1.2@1423.23,3170 1410,3170 1306,3066 1306,2904 1470,2740 1470,2660 ; U1.9@1814.88,2418.74 1711.26,2418.74 1470,2660
  Top Layer w9.84: VR1.2@1423.23,3170 1501.49,3091.73 R13.1@1501.49,3020
  Bottom Layer w8: v1(820,1770) 870,1820 v1(870,2660)
PJ.0: PORT_J.1 U1.30 | length 2657
  Top Layer w8: v1(1930,1720) 1930,1930 1962.52,1962.52 U1.30@1962.52,2034.88
  Bottom Layer w8: v1(1930,1720) 2254.2,1720 2400.2,1866 2505.8,1866 2944,2304.2 2944,2409.8 3158.2,2624 3564.2,2624 3640,2699.8 3640,2780 PORT_J.1@3690,2830
PJ.1: PORT_J.2 U1.31 | length 2576.7
  Top Layer w8: v1(1960,1690) 1960,1930 1982.2,1952.2 U1.31@1982.2,2034.88
  Bottom Layer w8: v1(1960,1690) 2250,1690 2412,1852 2511.6,1852 2958,2298.4 2958,2404 3164,2610 3570,2610 PORT_J.2@3690,2730
RF_GPIO_10: PORT_6_8.6 R46.2 U1.60 | length 4391.6
  Top Layer w8: PORT_6_8.6@350,1350 490,1350 1090,1950 1090,1950.2 1160,2020.2 v1(1160,2070) ; v1(610,3340) R46.2@610,3508.5 ; v1(2240,2250) 2270.94,2280.94 U1.60@2425.12,2280.94
  Bottom Layer w8: v1(610,3340) 630,3320 671.01,3320 1032.76,2958.24 1032.76,2447.24 1160,2320 v1(1160,2070) 1160,2030 1304,1886 1936.4,1886 2220,2169.6 2220,2230 v1(2240,2250)
RF_GPIO_13: PORT_1_4.2 R53.2 U1.65 | length 4855.3
  Top Layer w8: PORT_1_4.2@350,1950 500,2100 940,2100 960,2120 1090,2120 1140,2170 v1(1250,2170) ; R53.2@380,2901.5 v1(380,3380) ; v1(2200,2330) 2249.37,2379.37 U1.65@2425.12,2379.37
  Bottom Layer w8: v1(380,3380) 430,3430 620.4,3430 1074.76,2975.64 1074.76,2464.63 1206.25,2333.14 1206.25,2263.95 1250,2220.2 v1(1250,2170) 1250,2100 1270,2080 1270,2029.6 1371.6,1928 1919.01,1928 2160,2168.99 2160,2290 v1(2200,2330)
RF_GPIO_17: PORT_1_4.1 R52.2 U1.66 | length 5166.5
  Top Layer w8: PORT_1_4.1@250,1950 300,1900 370,1900 550,2080 950,2080 970,2100 1089.8,2100 1139.8,2150 1230,2150 v1(1310,2070) ; R52.2@320,2901.5 v1(320,3380) ; v1(2160,2330) 2229.06,2399.06 U1.66@2425.12,2399.06
  Bottom Layer w8: v1(320,3380) 390,3450 620.2,3450 1088.76,2981.44 1088.76,2470.43 1220.25,2338.94 1220.25,2269.75 1310,2180 1310,2009.4 1377.4,1942 1913.21,1942 2140,2168.79 2140,2310 v1(2160,2330)
RF_GPIO_81: PORT_6_8.7 R45.2 U1.61 | length 4566
  Top Layer w8: PORT_6_8.7@250,1250 300,1300 459.8,1300 1190,2030.2 v1(1190,2040) ; v1(550,3370) R45.2@550,3508.5 ; v1(2240,2290) 2250.63,2300.63 U1.61@2425.12,2300.63
  Bottom Layer w8: v1(550,3370) 640.8,3370 1046.76,2964.04 1046.76,2453.04 1178.25,2321.55 1178.25,2252.35 1190,2240.6 v1(1190,2040) 1330,1900 1930.6,1900 2200,2169.4 2200,2250 v1(2240,2290)
RF_GPIO_82: PORT_6_8.5 R49.2 U1.59 | length 5198.5
  Top Layer w8: R49.2@140,2901.5 v1(140,3300) ; PORT_6_8.5@250,1350 300,1400 520,1400 1130,2010 v1(1130,2100) ; v1(2280,2250) 2291.26,2261.26 U1.59@2425.12,2261.26
  Bottom Layer w8: v1(140,3300) 671.21,3300 1018.76,2952.44 1018.76,2441.44 1146,2314.2 1146,2116 v1(1130,2100) 1130,2018.39 1276.39,1872 1942.2,1872 2240,2169.8 2240,2210 v1(2280,2250)
RF_SPI1_MISO/RF_UART_TXD: PORT_2_3.2 R50.2 U1.50 | length 4242.4
  Top Layer w8: v1(199.59,3080.41) 200,3080 R50.2@200,2901.5 ; PORT_2_3.2@350,2350 360,2350 450,2260 820,2260 910,2350 v1(940,2350) ; v1(2100,1800) 2280,1800 2378,1898 2378,1971.6 2356.22,1993.38 U1.50@2356.22,2034.88
  Bottom Layer w8: v1(199.59,3080.41) 752.21,3080.41 920.76,2911.85 920.76,2369.24 v1(940,2350) 940,2210 964,2186 964,2045.8 1235.8,1774 2044,1774 2070,1800 v1(2100,1800)
RF_SPI1_MOSI/RF_UART_RXD: PORT_2_3.1 R51.2 U1.51 | length 4405.4
  Top Layer w8: PORT_2_3.1@250,2350 300,2300 380,2300 440,2240 840,2240 v1(910,2310) ; R51.2@260,2901.5 v1(260,3040) ; v1(2130,1770) 2270,1770 2500,2000 2500,2070 2466.22,2103.78 U1.51@2425.12,2103.78
  Bottom Layer w8: v1(260,3040) 286.41,3066.41 746.41,3066.41 906.76,2906.05 906.76,2313.24 v1(910,2310) 910,2220 950,2180 950,2040 1230,1760 2060,1760 2070,1770 v1(2130,1770)
RF_SPI1_SCLK: PORT_2_3.3 R47.2 U1.49 | length 4086.2
  Top Layer w8: PORT_2_3.3@250,2250 300,2200 890,2200 v1(970,2280) ; v1(670,3110) R47.2@670,3508.5 ; v1(2130,1830) 2290,1830 2364,1904 2364,1965.8 2336.54,1993.26 U1.49@2336.54,2034.88
  Bottom Layer w8: v1(670,3110) 685.59,3094.41 758.01,3094.41 934.76,2917.65 934.76,2405.24 970,2370 v1(970,2280) 980,2270 980,2049.6 1241.6,1788 2028,1788 2070,1830 v1(2130,1830)
RF_SPI_MISO: J601.4 PORT_2_3.6 R57.2 U1.41 | length 5272.1
  Top Layer w8: PORT_2_3.6@350,2150 380,2180 900,2180 960,2240 1080,2240 v1(1100,2260) ; R57.2@620,2901.5 v1(620,3250) ; U1.41@2179.05,2034.88 2179.05,1989.05 2140,1950 v1(2130,1950) 2070,1950 2010,1890 2010,1699.8 2145.8,1564 2425.8,1564 2685.8,1304 2766,1304 J601.4@2850,1220
  Bottom Layer w8: v1(620,3250) 630,3260 671.61,3260 990.76,2940.85 990.76,2429.84 1100,2320.6 v1(1100,2260) 1080,2240 1080,2028.79 1264.79,1844 1964,1844 2070,1950 v1(2130,1950)
RF_SPI_MOSI: J601.2 PORT_2_3.5 R56.2 U1.40 | length 5396.7
  Top Layer w8: PORT_2_3.5@250,2150 300,2100 368,2100 428,2160 910,2160 970,2220 1080,2220 v1(1110,2190) ; R56.2@560,2901.5 v1(560,3250) ; U1.40@2159.37,2034.88 2159.37,1999.37 2140,1980 v1(2100,1980) 2070,1980 1990,1900 1990,1700 2140,1550 2420,1550 J601.2@2750,1220
  Bottom Layer w8: v1(560,3250) 590,3280 671.41,3280 1004.76,2946.65 1004.76,2435.64 1132,2308.4 1132,2212 v1(1110,2190) 1100,2180 1100,2028.59 1270.59,1858 1948,1858 2070,1980 v1(2100,1980)
RF_SPI_SCLK: J601.6 PORT_2_3.7 R55.2 U1.42 | length 5477.8
  Top Layer w8: PORT_2_3.7@250,2050 300,2000 370,2000 490,2120 930,2120 960,2150 v1(1050,2150) ; R55.2@500,2901.5 v1(500,3210) ; U1.42@2198.74,2034.88 2198.74,1968.74 2150,1920 v1(2100,1920) 2070,1920 2030,1880 2030,1699.6 2151.6,1578 2431.6,1578 2691.6,1318 2852,1318 J601.6@2950,1220
  Bottom Layer w8: v1(500,3210) 510,3220 691.81,3220 976.76,2935.05 976.76,2424.04 1070,2330.8 1070,2270 1050,2250 v1(1050,2150) 1050,2038.99 1258.99,1830 1980,1830 2070,1920 v1(2100,1920)
RST/NMI/SBWTDIO: C1.2 J402.4 MCU_RESET.2 R1.1 SBW.4 U1.29 | length 1808.9
  Top Layer w8: J402.4@900,1220 900,1390 1086.93,1576.93 MCU_RESET.2@1490,1576.93 1621.57,1576.93 1630,1568.51 1630,1511.5 1633.5,1515 SBW.4@1770,1515 1835,1515 1904,1584 1904,1934 1942.83,1972.83 U1.29@1942.83,2034.88
TARGET_3V3: C3.2 C5.1 C9.2 C32.1 C409.1 C411.1 ESI.2 J401.4 JP13.1 JP14.1 PORT_9/ESI.2 R1.2 R3.2 R40.2 R41.2 R65.2 RF2.7 RF2.9 SBW.2 U1.27 U1.58 U1.99 | length 1494.4
  Top Layer w10: v1(1683.62,2726.38) C9.2@1740,2726.38 1850.99,2726.38 1903.46,2673.91 U1.99@1903.46,2645.12 ; v1(1715.78,1986.38) C3.2@1780,1986.38 1886.38,1986.38 1903.46,2003.46 U1.27@1903.46,2034.88 ; U1.58@2425.12,2241.57 2491.57,2241.57 2508.51,2258.51 v1(2508.51,2308.51)
  Top Layer w20: RF2.7@304.5,3731.5 RF2.9@354.5,3731.5 354.5,3575.99 350,3571.5 v1(418.5,3571.5) ; R40.2@461.49,1821.5 R41.2@581.49,1821.5 ; R1.2@1630,1623.62 1696.38,1623.62 1705,1615 SBW.2@1770,1615 ; C411.1@2181.5,1400 2201.18,1380.32 C409.1@2201.18,1320 2200,1318.82 J401.4@2200,1220 ; R65.2@2573.62,2800 v1(2640,2800) ; v1(2971.5,1898.5) R3.2@3030,1898.5
  other v1: 521.49,1822.99
TARGET_GND: BUT.1 BUT.2 C1.1 C3.1 C5.2 C9.1 C32.2 C33.1 C36.2 C409.2 C411.2 ESI.1 ESI.15 J401.2 MCU_RESET.1 NT0.2 pad.0@150,1650 pad.0@150,1750 pad.0@150,2350 PORT_1_4.3 PORT_1_4.4 PORT_6_8.4 PORT_9/ESI.1 PORT_9/ESI.15 R63.1 RF1.1 RF1.19 RF2.2 SBW.5 U1.26 U1.57 U1.98 VR1.1 VR1.3 | length 2128
  Top Layer w10: v1(269.5,3513.5) C32.2@350,3513.5 ; MCU_RESET.1@1490,1443.07 1495.44,1448.51 1678.51,1448.51 1695,1465 SBW.5@1770,1465 ; v1(1683.62,2773.62) C9.1@1740,2773.62 1826.38,2773.62 1923.15,2676.85 U1.98@1923.15,2645.12 ; v1(1716.38,2033.62) C3.1@1780,2033.62 1781.26,2034.88 U1.26@1883.78,2034.88 ; U1.57@2425.12,2221.89 2551.89,2221.89 2571.5,2241.5 v1(2571.5,2308.5)
  Top Layer w20: v1(154.5,2444.5) RF1.1@154.5,2531.5 ; RF2.2@154.5,3866.5 v1(154.5,3965.5) ; v1@604.5,2454.5 RF1.19@604.5,2531.5 ; VR1.1@1572.83,3227.09 VR1.3@1572.83,3112.91 ; C33.1@1580,3023.47 1572.83,3030.63 VR1.3@1572.83,3112.91 ; v1(1652.91,3112.91) VR1.3@1572.83,3112.91 ; J401.2@2100,1220 2100,1318.82 C409.2@2098.82,1320 2098.82,1380.31 C411.2@2118.5,1400 ; NT0.2@2190,3330 v1(2250,3330) ; R63.1@2653.62,2710 v1(2710,2710) ; v1(3100,1840) 3100,1898.5 3168.5,1898.5
  Top Layer w30: BUT.1@3174.8,1861.89 BUT.2@3174.8,1928.82
  Mid-Layer 1 w10: v1@1710,2040 v1(1716.38,2033.62)
  other v1: 600,2450
TARGET_READY_IN: J601.7 U200.43 | length 439.9
  Top Layer w8: J601.7@3050,1120 3050,1050 3086.87,1013.13 U200.43@3086.87,695.41
TEST/SBWTCK: J402.2 SBW.3 U1.28 | length 1774.3
  Top Layer w8: J402.2@800,1220 800,1320 1090,1610 v1(1390,1610) ; SBW.3@1770,1565 1825,1565 1880,1620 1880,1940 1923.15,1983.15 U1.28@1923.15,2034.88
  Bottom Layer w8: v1(1390,1610) 1650,1610 1695,1565 SBW.3@1770,1565
UART0_RXD: J402.8 PORT_1_4.8 SBW.1 U1.1 | length 3886.8
  Top Layer w8: v1(1580,2500) 1220,2500 1150,2430 1150,2310 1350,2110 1350,1820 1460,1710 1725,1710 SBW.1@1770,1665 ; v1(1740,2610) 1750,2610 1783.78,2576.22 U1.1@1814.88,2576.22
  Bottom Layer w8: PORT_1_4.8@350,1650 940,1650 1100,1490 ; J402.8@1100,1220 1100,1490 ; v1(1580,2500) 1630,2500 1660,2470 1730,2470 1760,2500 1760,2540 1740,2560 v1@1740,2620 ; SBW.1@1770,1665 1275,1665 1100,1490
UART0_TXD: J402.6 PORT_1_4.7 SBW.6 U1.100 | length 4375.1
  Top Layer w8: v1(1000,1385) v1(1165,1385) ; v1(1610,2470) 1210,2470 1164,2424 1164,2315.8 1364,2115.8 1364,1825.8 1465.8,1724 1796,1724 1840,1680 v1(1840,1660) ; U1.100@1883.78,2645.12 1883.78,2456.22 v1(1890,2450)
  Bottom Layer w8: PORT_1_4.7@250,1650 300,1600 920,1600 1000,1520 v1(1000,1385) J402.6@1000,1220 ; v1(1165,1385) 1195,1415 1815,1415 1840,1440 v1(1840,1660) ; v1(1610,2470) 1617.91,2470 1637.91,2450 v1(1890,2450)
USB_SHIELD: J400.6 J400.7 J400.8 J400.9 J400.10 J400.11 R405.1 | length 618.3
  Top Layer w7.87: J400.9@2083.94,121.38 R405.1@2160,121.38
  Top Layer w30: J400.8@1755.28,111.06 1755.28,172.64 v1(1792.4,209.76) ; J400.8@1756.97,109.37 1767.6,120 v1(1880,120) v1(1950,120) v1(2075,120) 2075,171.26 v1(2036.5,209.76)
  other v1: 1757.13,119.76
VBUS: C209.1 C401.1 C402.1 C414.1 C415.1 J400.1 R110.2 R418.1 U100.53 U200.53 U400.1 U402.8 U403.3 U403.5 | length 5267.8
  Top Layer w7.87: 485,720 552.1,652.9 U100.53@599.83,652.9 ; v1(680,150) R110.2@680,211.38 ; C209.1@2631.18,540 2680,540 2710,570 2850,570 2867.14,587.14 U200.53@2958.92,587.14
  Top Layer w8: v1(460,830) 485,805 485,720
  Top Layer w10: C415.1@1938.35,525.32 v1(1938.35,578.35) 1954.68,594.68 U403.3@1954.68,630.63 ; U403.5@1985,650.32 v1(2029.84,650.31)
  Top Layer w12: J400.1@1965.63,204.68 J400.1@1965.63,214.68 1966.02,215.08 U400.1@1966.02,295 1985,295 2048.62,358.62 C402.1@2075,358.62
  Top Layer w15: C415.1@1938.35,525.32 1938.35,481.65 1955,465 2005,465 2075,395 2075,358.62 2508.62,358.62 2630,480 2630,538.82 C209.1@2631.18,540 ; v1(2260,358.62) 2260,420 2293.62,453.62 R418.1@2293.62,500 ; U402.8@2298.39,584.88 2298.39,504.76 R418.1@2293.62,500 ; C414.1@2410,518.5 2391.5,500 R418.1@2293.62,500
  Bottom Layer w10: v1(1938.35,578.35) 1998.35,578.35 2029.84,609.84 v1(2029.84,650.31)
  Bottom Layer w15: v1(460,830) 430,830 410,810 410,230 490,150 v1(680,150) 745,85 2195,85 2260,150 v1(2260,358.62)
pads on no net: J400.4 RF1.2 RF1.4 RF1.6 RF1.8 RF1.11 RF1.13 RF1.15 RF1.17 RF1.21 RF1.22 RF2.1 RF2.3 RF2.4 RF2.5 RF2.6 RF2.8 RF2.10 RF2.11 RF2.12 RF2.13 RF2.14 RF2.16 RF2.20 RF2.21 RF2.22 U1.47@1824.72,2635.28 U100.3 U100.4 U100.5 U100.6 U100.7 U100.8 U100.10 U100.12 U100.13 U100.18 U100.19 U100.22 U100.23 U100.24 U100.25 U100.26 U100.27 U100.28 U100.29 U100.30 U100.31 U100.32 U100.33 U100.34 U100.35 U100.36 U100.41 U100.42 U100.45 U100.46 U100.47 U100.48 U200.1 U200.2 U200.3 U200.4 U200.5 U200.6 U200.7 U200.8 U200.9 U200.10 U200.12 U200.13 U200.22 U200.23 U200.24 U200.25 U200.26 U200.27 U200.28 U200.29 U200.30 U200.31 U200.32 U200.33 U200.41 U200.42 U200.47 U200.48 U400.2 U401.5 U401.9 U401.13 U401.17 U401.21 U401.32 U402.2 U402.6 U402.7

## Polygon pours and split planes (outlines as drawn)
AGND on Mid-Layer 1 "Top Layer-No Net" (solid, pour order 24): 2140,2610 2140,2700 1930,2910 1930,3290 2700,3290 2700,2850 2450,2850 2280,2680 2280,2610
GND on Mid-Layer 1 "Mid-Layer 1-No Net 1" (solid, pour order 28): 680,670 680,490 870,490 870,680 680,680
GND on Mid-Layer 1 "Mid-Layer 1-No Net 2" (solid, pour order 29): 1310,720 1310,570 1460,570 1460,720 1310,720
GND on Mid-Layer 1 "Mid-Layer 1-No Net 3" (solid, pour order 30): 2210,680 2210,580 2320,580 2320,680 2210,680
GND on Mid-Layer 1 "Mid-Layer 1-No Net 4" (solid, pour order 31): 3030,620 3030,410 3240,410 3240,620 3030,620
TARGET_GND on Mid-Layer 1 "BotLayer-Netled7_2" (solid, remove dead copper, pour order 27): 50,4730 50,1210 70,1190 3980,1190 4000,1210 4000,4730 3980,4750 3120,4750 3100,4730 3100,3420 3080,3400 920,3400 900,3420 900,4730 880,4750 70,4750
GND on Mid-Layer 1 "Mid-Layer 1-No Net" (solid, remove dead copper, pour order 33): 70,50 50,70 50,1130 70,1150 3980,1150 4000,1130 4000,70 3980,50
AGND on Top Layer "Top Layer-No Net" (solid, pour order 25): 2140,2610 2140,2700 1930,2910 1930,3290 2700,3290 2700,2850 2450,2850 2300,2700 2300,2610
TARGET_3V3 on Mid-Layer 2 "BotLayer-Netled7_2" (solid, remove dead copper, pour order 26): 50,4730 50,1210 70,1190 3980,1190 4000,1210 4000,4730 3980,4750 3120,4750 3100,4730 3100,3420 3080,3400 920,3400 900,3420 900,4730 880,4750 70,4750
3V3 on Mid-Layer 2 "Mid-Layer 1-No Net" (solid, remove dead copper, pour order 32): 70,50 50,70 50,1130 70,1150 3980,1150 4000,1130 4000,70 3980,50

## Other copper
Top Layer:
  pour cut-out: 979.76,786.97 575,786.97 575,381.24 979.76,381.24
  pour cut-out: 1277.56,540 1492.13,540 1492.13,754.57 1277.56,754.57
  pour cut-out: 2940,312.95 3345,312.95 3345,717.16 2940,717.16

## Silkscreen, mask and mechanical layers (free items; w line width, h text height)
Top Overlay:
  lines w10: 70,1170 420,1170 430,1170 730,1170 ; 580,3440 580,3470 ; 610,3470 580,3470 ; 890,3420 650,3420 630,3420 580,3470 ; 1170,1170 2030,1170 ; 2270,1170 2670,1170 ; 3130,1170 4000,1170
  text "1" at 3350,3780 h40
  text "2" at 3630,3780 h40
  text "15" at 3304,3070 h40
  text "16" at 3630,3070 h40
  text "TEST_SBW" at 820,1290 h40 r90
  text "RST_SBW" at 920,1290 h40 r90
  text "EZ_RXD" at 1020,1290 h40 r90
  text "EZ_TXD" at 1120,1290 h40 r90
  text "COMM_RX" at 2770,1290 h40 r90
  text "COMM_TX" at 2870,1290 h40 r90
  text "COMM_RDY_OUT" at 2970,1290 h40 r90
  text "COMM_RDY_IN" at 3070,1290 h40 r90
  text "TIDM-3LC-METER-CONV" at 3940,1240 h50 r90
  text "GND" at 2020,1200 h40 r90
  text "3V3" at 2320,1200 h40 r90
  text "Debug Circuit" at 1500,1090 h78.74
  text "GND" at 3880,1000 h40
  text "TX" at 3320,980 h40 r90
  text "RX" at 3420,980 h40 r90
  text "GND" at 3210,940 h40 r90
  text "DRDY" at 3590,880 h40 r90
  text "SCL" at 3720,880 h40 r90
  text "SDA" at 3830,880 h40 r90
  text "JTAG" at 220,730 h40 r90
  text "LED3" at 3540,460 h40 r90
  text "LED2" at 3610,460 h40 r90
  text "LED1" at 3680,460 h40 r90
  text "LED0" at 3750,460 h40 r90
  text "Communications" at 3880,390 h40 r90
  text "MCU_RESET" at 3420,330 h40
  text "JTAG" at 2860,170 h40
  text "USB" at 1400,100 h40
  text "eZ-FET Lite" at 490,50 h40
Bottom Overlay:
  text "PORT_2_3" at 1550,4500 h51.18
  text "PORT_9/ESI" at 3350,4500 h51.18
  text "P2.1" at 1040,4420 h51.18
  text "2" at 1150,4420 h51.18
  text "P2.0" at 1440,4420 h51.18
  text "1" at 1550,4420 h51.18
  text "11" at 2650,4420 h51.18
  text "GND" at 3100,4420 h51.18
  text "1,15" at 3350,4420 h51.18
  text "ESICH3/ESITEST3" at 2450,4419.21 h51.18
  text "P2.3" at 1040,4340 h51.18
  text "4" at 1150,4340 h51.18
  text "P2.2" at 1440,4340 h51.18
  text "3" at 1550,4340 h51.18
  text "ESICH2/ESITEST2" at 2450,4340 h51.18
  text "12" at 2650,4340 h51.18
  text "VCC_IO" at 3100,4340 h51.18
  text "2" at 3350,4340 h51.18
  text "P3.5" at 1040,4260 h51.18
  text "6" at 1150,4260 h51.18
  text "P3.4" at 1440,4260 h51.18
  text "5" at 1550,4260 h51.18
  text "ESICH1/ESITEST1" at 2450,4260 h51.18
  text "13" at 2650,4260 h51.18
  text "ESIVSS" at 3100,4260 h51.18
  text "3" at 3350,4260 h51.18
  text "P3.7" at 1040,4180 h51.18
  text "8" at 1150,4180 h51.18
  text "P3.6" at 1440,4180 h51.18
  text "7" at 1550,4180 h51.18
  text "ESICH0/ESITEST0" at 2450,4180 h51.18
  text "14" at 2650,4180 h51.18
  text "ESIVCC" at 3100,4180 h51.18
  text "4" at 3350,4180 h51.18
  text "ESITEST4" at 2450,4100 h51.18
  text "16" at 2650,4100 h51.18
  text "ESICOM" at 3100,4100 h51.18
  text "5" at 3350,4100 h51.18
  text "ESICI" at 3100,4020 h51.18
  text "6" at 3350,4020 h51.18
  text "PORT_6_8" at 1550,3950 h51.18
  text "PORT_1_4" at 2450,3950 h51.18
  text "ESICI3" at 3100,3940 h51.18
  text "7" at 3350,3940 h51.18
  text "P6.1" at 1040,3870 h51.18
  text "2" at 1150,3870 h51.18
  text "P6.0" at 1440,3870 h51.18
  text "1" at 1550,3870 h51.18
  text "P1.1" at 1940,3870 h51.18
  text "2" at 2050,3870 h51.18
  text "P1.0" at 2340,3870 h51.18
  text "1" at 2450,3870 h51.18
  text "ESICI2" at 3100,3860 h51.18
  text "8" at 3350,3860 h51.18
  text "GND" at 1040,3790 h51.18
  text "4" at 1150,3790 h51.18
  text "P6.2" at 1440,3790 h51.18
  text "3" at 1550,3790 h51.18
  text "GND" at 1940,3790 h51.18
  text "4" at 2050,3790 h51.18
  text "GND" at 2340,3790 h51.18
  text "3" at 2450,3790 h51.18
  text "ESICI1" at 3100,3780 h51.18
  text "9" at 3350,3780 h51.18
  text "P8.5" at 1040,3710 h51.18
  text "6" at 1150,3710 h51.18
  text "P8.4" at 1440,3710 h51.18
  text "5" at 1550,3710 h51.18
  text "P1.7" at 1940,3710 h51.18
  text "6" at 2050,3710 h51.18
  text "P1.6" at 2340,3710 h51.18
  text "5" at 2450,3710 h51.18
  text "ESICI0" at 3100,3700 h51.18
  text "10" at 3350,3700 h51.18
  text "P8.7" at 1040,3630 h51.18
  text "8" at 1150,3630 h51.18
  text "P8.6" at 1440,3630 h51.18
  text "7" at 1550,3630 h51.18
  text "P4.3" at 1940,3630 h51.18
  text "8" at 2050,3630 h51.18
  text "P4.2" at 2340,3630 h51.18
  text "7" at 2450,3630 h51.18
  text "PORT_J" at 1550,3270 h51.18
  text "PJ.1" at 1040,3190 h51.18
  text "2" at 1150,3190 h51.18
  text "PJ.0" at 1440,3190 h51.18
  text "1" at 1550,3190 h51.18
  text "PJ.3" at 1040,3110 h51.18
  text "4" at 1150,3110 h51.18
  text "PJ.2" at 1440,3110 h51.18
  text "3" at 1550,3110 h51.18
  text "PJ.5" at 1040,3030 h51.18
  text "6" at 1150,3030 h51.18
  text "PJ.4" at 1440,3030 h51.18
  text "5" at 1550,3030 h51.18
  text "PJ.7" at 1040,2950 h51.18
  text "8" at 1150,2950 h51.18
  text "PJ.6" at 1440,2950 h51.18
  text "7" at 1550,2950 h51.18
Top Solder:
Bottom Solder:
Mechanical 1:
  the board outline again, w1
Mechanical 2:
Mechanical 5:
  text ".Designator" at 1240,470 h40 r90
